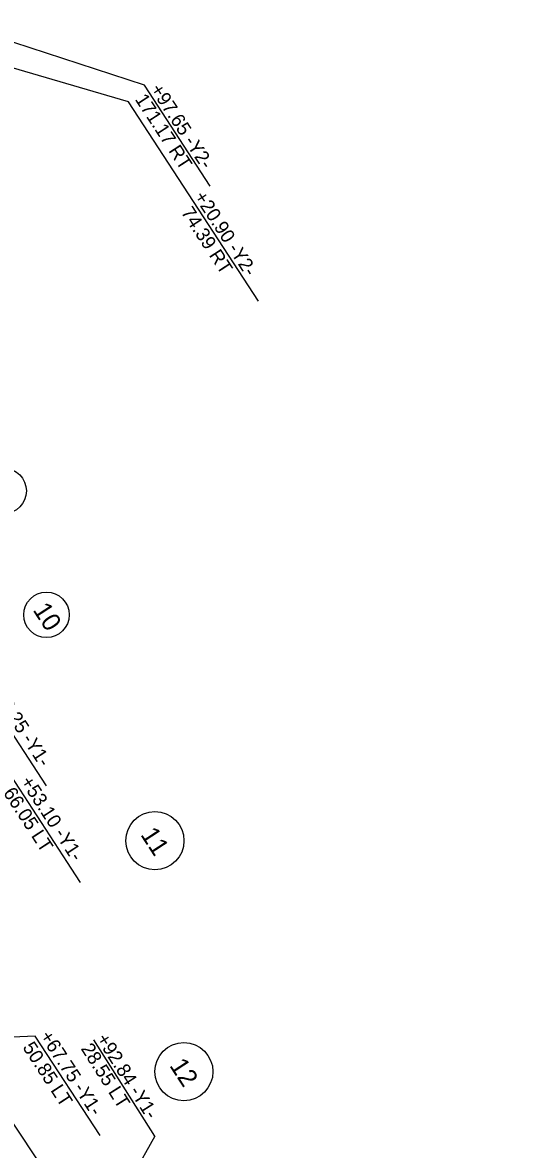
# Model space of a CAD drawing. Extents: x 1638966 to 1642158, y 841755 to 844938.
# Drawn here: x 1640735 to 1640955.3, y 843231.6 to 843723.1 of the extents above; entities that cross this region are included whole.
import ezdxf

# ---------------------------------------------------------------- set-up
doc = ezdxf.new("R2010")
doc.units = 0
for name, color, linetype in [('Exist Building', 7, 'Continuous'), ('Exist Guardrail Text', 7, 'Continuous'), ('Exist Structure Minor Pipes CMP 18 Inch Text', 7, 'Continuous'), ('Exist Structure Minor Pipes CMP 24 Inch', 7, 'Continuous'), ('Exist Structure Minor Pipes RCP 24 Inch', 7, 'Continuous')]:
    doc.layers.add(name, color=color, linetype=linetype)

msp = doc.modelspace()

# ---------------------------------------------------------------- linework, layer by layer
at = {"layer": 'Exist Building'}
for centre, radius in [((1640726.79, 843518.8), 9.91), ((1640745.42, 843464.76), 9.91), ((1640792.74, 843366.24), 12.69), ((1640805.38, 843265.5), 12.69)]:
    msp.add_circle(centre, radius, dxfattribs=at)
at = {"layer": 'Exist Guardrail Text'}
for q in [(1640766.07, 843279.43), (1640749.71, 843161.13)]:
    msp.add_line((1640792.68, 843237.37), q, dxfattribs=at)
at = {"layer": 'Exist Structure Minor Pipes CMP 18 Inch Text'}
for p, q in [((1640781.19, 843688.57), (1640524.73, 843763.24)), ((1640788.22, 843695.73), (1640639.54, 843744.24)), ((1640816.92, 843651.76), (1640788.22, 843695.73)), ((1640837.95, 843601.59), (1640781.19, 843688.57))]:
    msp.add_line(p, q, dxfattribs=at)
at = {"layer": 'Exist Structure Minor Pipes CMP 24 Inch'}
for p, q in [((1640745.49, 843390.15), (1640715.06, 843436.77)), ((1640760.24, 843347.99), (1640724.15, 843403.3)), ((1640768.84, 843237.66), (1640740.55, 843281.01))]:
    msp.add_line(p, q, dxfattribs=at)
msp.add_lwpolyline([(1640740.55, 843281.01), (1640706.65, 843279.59)], dxfattribs=at)
at = {"layer": 'Exist Structure Minor Pipes RCP 24 Inch'}
msp.add_lwpolyline([(1640706.65, 843279.5), (1640710.92, 843272.69), (1640777.02, 843173.29), (1640955.29, 842892.74)], dxfattribs=at)

# ---------------------------------------------------------------- texts
at = {"layer": 'Exist Building'}
for s, p in [('10', (1640739.27, 843466.88)), ('11', (1640786.23, 843368.9)), ('12', (1640798.88, 843268.16))]:
    msp.add_text(s, height=8, rotation=303.0906, dxfattribs=at).set_placement(p)
at = {"layer": 'Exist Guardrail Text'}
for s, p in [('28.55 LT', (1640760.24, 843275.57)), ('+92.84 -Y1-', (1640767, 843279.85))]:
    msp.add_text(s, height=6, rotation=302.3172, dxfattribs=at).set_placement(p)
at = {"layer": 'Exist Structure Minor Pipes CMP 18 Inch Text'}
for s, p in [('+97.65 -Y2-', (1640790.55, 843693.99)), ('171.17 RT', (1640783.85, 843689.62)), ('+20.90 -Y2-', (1640809.62, 843647.18)), ('74.39 RT', (1640803.95, 843640.32))]:
    msp.add_text(s, height=6, rotation=303.1259, dxfattribs=at).set_placement(p)
at = {"layer": 'Exist Structure Minor Pipes CMP 24 Inch'}
for s, p in [('+53.25 -Y1-', (1640719.79, 843433.24)), ('+53.10 -Y1-', (1640733.9, 843392.03)), ('66.05 LT', (1640726.36, 843387.11)), ('+67.75 -Y1-', (1640742.35, 843281)), ('50.85 LT', (1640734.82, 843276.08))]:
    msp.add_text(s, height=6, rotation=303.1259, dxfattribs=at).set_placement(p)

doc.saveas('drawing.dxf')
